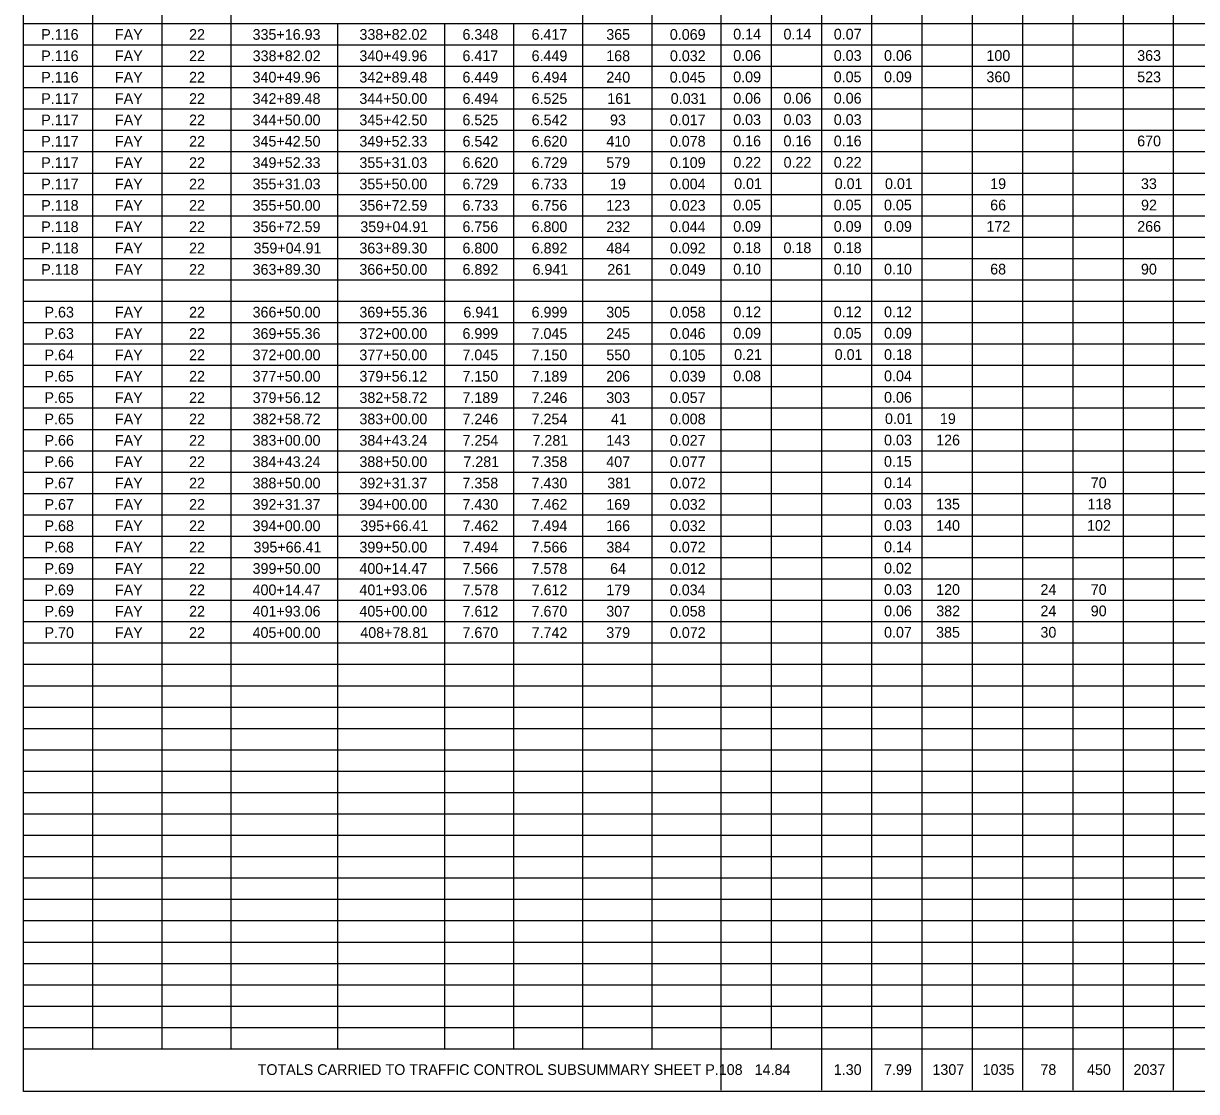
# Model space of a CAD drawing. Extents: x 12522 to 13018, y 1124 to 1902.
# Drawn here: x 12873.15 to 12888.52, y 1804.65 to 1818.65 of the extents above; entities that cross this region are included whole.
import ezdxf

# ---------------------------------------------------------------- set-up
doc = ezdxf.new("R2010")
doc.units = 0
for name, color, linetype in [('SC_Scratch1', 7, 'Continuous'), ('SH_Data', 7, 'Continuous'), ('SH_Text', 7, 'Continuous')]:
    doc.layers.add(name, color=color, linetype=linetype)

msp = doc.modelspace()

# ---------------------------------------------------------------- linework, layer by layer
at = {"layer": 'SC_Scratch1'}
msp.add_lwpolyline([(12873.148, 1825.65), (12903.648, 1825.65), (12903.648, 1804.65), (12873.148, 1804.65)], close=True, dxfattribs=at)
at = {"layer": 'SH_Data'}
for p, q in [((12882.289, 1825.65), (12882.289, 1804.667)), ((12875.865, 1825.09), (12875.865, 1805.21)), ((12880.477, 1825.09), (12880.477, 1805.21)), ((12881.383, 1825.09), (12881.383, 1805.21)), ((12883.607, 1825.09), (12883.607, 1804.667)), ((12884.265, 1825.09), (12884.265, 1804.667)), ((12884.924, 1825.09), (12884.924, 1804.667)), ((12885.583, 1825.09), (12885.583, 1804.667)), ((12886.242, 1825.09), (12886.242, 1804.667)), ((12886.901, 1825.09), (12886.901, 1804.667)), ((12887.56, 1825.09), (12887.56, 1804.667)), ((12888.218, 1825.09), (12888.218, 1804.667)), ((12882.948, 1822.85), (12882.948, 1805.21)), ((12874.054, 1821.73), (12874.054, 1805.21)), ((12874.96, 1821.73), (12874.96, 1805.21)), ((12873.148, 1818.65), (12903.668, 1818.65)), ((12877.265, 1818.65), (12877.265, 1805.21)), ((12878.665, 1818.65), (12878.665, 1805.21)), ((12879.571, 1818.65), (12879.571, 1805.21)), ((12873.148, 1818.37), (12903.668, 1818.37)), ((12873.148, 1818.09), (12903.668, 1818.09)), ((12873.148, 1817.81), (12903.668, 1817.81)), ((12873.148, 1817.53), (12903.668, 1817.53)), ((12873.148, 1817.25), (12903.668, 1817.25)), ((12873.148, 1816.97), (12903.668, 1816.97)), ((12873.148, 1816.69), (12903.668, 1816.69)), ((12873.148, 1816.41), (12903.668, 1816.41)), ((12873.148, 1816.13), (12903.668, 1816.13)), ((12873.148, 1815.85), (12903.668, 1815.85)), ((12873.148, 1815.57), (12903.668, 1815.57)), ((12873.148, 1815.29), (12903.668, 1815.29)), ((12873.148, 1815.01), (12903.668, 1815.01)), ((12873.148, 1814.73), (12903.668, 1814.73)), ((12873.148, 1814.45), (12903.668, 1814.45)), ((12873.148, 1814.17), (12903.668, 1814.17)), ((12873.148, 1813.89), (12903.668, 1813.89)), ((12873.148, 1813.61), (12903.668, 1813.61)), ((12873.148, 1813.33), (12903.668, 1813.33)), ((12873.148, 1813.05), (12903.668, 1813.05)), ((12873.148, 1812.77), (12903.668, 1812.77)), ((12873.148, 1812.49), (12903.668, 1812.49)), ((12873.148, 1812.21), (12903.668, 1812.21)), ((12873.148, 1811.93), (12903.668, 1811.93)), ((12873.148, 1811.65), (12903.668, 1811.65)), ((12873.148, 1811.37), (12903.668, 1811.37)), ((12873.148, 1811.09), (12903.668, 1811.09)), ((12873.148, 1810.81), (12903.668, 1810.81)), ((12873.148, 1810.53), (12903.668, 1810.53)), ((12873.148, 1810.25), (12903.668, 1810.25)), ((12873.148, 1809.97), (12903.668, 1809.97)), ((12873.148, 1809.69), (12903.668, 1809.69)), ((12873.148, 1809.41), (12903.668, 1809.41)), ((12873.148, 1809.13), (12903.668, 1809.13)), ((12873.148, 1808.85), (12903.668, 1808.85)), ((12873.148, 1808.57), (12903.668, 1808.57)), ((12873.148, 1808.29), (12903.668, 1808.29)), ((12873.148, 1808.01), (12903.668, 1808.01)), ((12873.148, 1807.73), (12903.668, 1807.73)), ((12873.148, 1807.45), (12903.668, 1807.45)), ((12873.148, 1807.17), (12903.668, 1807.17)), ((12873.148, 1806.89), (12903.668, 1806.89)), ((12873.148, 1806.61), (12903.668, 1806.61)), ((12873.148, 1806.33), (12903.668, 1806.33)), ((12873.148, 1806.05), (12903.668, 1806.05)), ((12873.148, 1805.77), (12903.668, 1805.77)), ((12873.148, 1805.49), (12903.668, 1805.49)), ((12873.148, 1805.21), (12903.668, 1805.21))]:
    msp.add_line(p, q, dxfattribs=at)

# ---------------------------------------------------------------- texts
at = {"layer": 'SH_Text'}
for s, p in [('P.116', (12873.381, 1818.436)), ('FAY', (12874.347, 1818.436)), ('22', (12875.319, 1818.436)), ('335+16.93', (12876.151, 1818.436)), ('338+82.02', (12877.552, 1818.436)), ('6.348', (12878.902, 1818.436)), ('6.417', (12879.808, 1818.436)), ('365', (12880.787, 1818.436)), ('0.069', (12881.62, 1818.436)), ('0.14', (12882.451, 1818.44)), ('0.14', (12883.11, 1818.44)), ('0.07', (12883.769, 1818.44)), ('P.116', (12873.381, 1818.156)), ('FAY', (12874.347, 1818.156)), ('22', (12875.319, 1818.156)), ('338+82.02', (12876.152, 1818.156)), ('340+49.96', (12877.551, 1818.156)), ('6.417', (12878.902, 1818.156)), ('6.449', (12879.808, 1818.156)), ('168', (12880.787, 1818.156)), ('0.032', (12881.621, 1818.156)), ('0.06', (12882.451, 1818.16)), ('0.03', (12883.769, 1818.16)), ('0.06', (12884.428, 1818.16)), ('100', (12885.77, 1818.16)), ('363', (12887.746, 1818.16)), ('P.116', (12873.381, 1817.876)), ('FAY', (12874.347, 1817.876)), ('22', (12875.319, 1817.876)), ('340+49.96', (12876.151, 1817.876)), ('342+89.48', (12877.551, 1817.876)), ('6.449', (12878.902, 1817.876)), ('6.494', (12879.808, 1817.876)), ('240', (12880.788, 1817.876)), ('0.045', (12881.619, 1817.876)), ('0.09', (12882.451, 1817.88)), ('0.05', (12883.768, 1817.88)), ('0.09', (12884.428, 1817.88)), ('360', (12885.77, 1817.88)), ('523', (12887.746, 1817.88)), ('P.117', (12873.381, 1817.596)), ('FAY', (12874.347, 1817.596)), ('22', (12875.319, 1817.596)), ('342+89.48', (12876.151, 1817.596)), ('344+50.00', (12877.551, 1817.596)), ('6.494', (12878.903, 1817.596)), ('6.525', (12879.808, 1817.596)), ('161', (12880.8, 1817.596)), ('0.031', (12881.632, 1817.596)), ('0.06', (12882.451, 1817.6)), ('0.06', (12883.11, 1817.6)), ('0.06', (12883.769, 1817.6)), ('P.117', (12873.381, 1817.316)), ('FAY', (12874.347, 1817.316)), ('22', (12875.319, 1817.316)), ('344+50.00', (12876.151, 1817.316)), ('345+42.50', (12877.551, 1817.316)), ('6.525', (12878.902, 1817.316)), ('6.542', (12879.809, 1817.316)), ('93', (12880.836, 1817.316)), ('0.017', (12881.62, 1817.316)), ('0.03', (12882.451, 1817.32)), ('0.03', (12883.11, 1817.32)), ('0.03', (12883.769, 1817.32)), ('P.117', (12873.381, 1817.036)), ('FAY', (12874.347, 1817.036)), ('22', (12875.319, 1817.036)), ('345+42.50', (12876.151, 1817.036)), ('349+52.33', (12877.551, 1817.036)), ('6.542', (12878.903, 1817.036)), ('6.620', (12879.808, 1817.036)), ('410', (12880.788, 1817.036)), ('0.078', (12881.62, 1817.036)), ('0.16', (12882.451, 1817.04)), ('0.16', (12883.11, 1817.04)), ('0.16', (12883.769, 1817.04)), ('670', (12887.746, 1817.04)), ('P.117', (12873.381, 1816.756)), ('FAY', (12874.347, 1816.756)), ('22', (12875.319, 1816.756)), ('349+52.33', (12876.151, 1816.756)), ('355+31.03', (12877.551, 1816.756)), ('6.620', (12878.902, 1816.756)), ('6.729', (12879.808, 1816.756)), ('579', (12880.787, 1816.756)), ('0.109', (12881.62, 1816.756)), ('0.22', (12882.452, 1816.76)), ('0.22', (12883.111, 1816.76)), ('0.22', (12883.769, 1816.76)), ('P.117', (12873.381, 1816.476)), ('FAY', (12874.347, 1816.476)), ('22', (12875.319, 1816.476)), ('355+31.03', (12876.151, 1816.476)), ('355+50.00', (12877.551, 1816.476)), ('6.729', (12878.902, 1816.476)), ('6.733', (12879.808, 1816.476)), ('19', (12880.836, 1816.476)), ('0.004', (12881.62, 1816.476)), ('0.01', (12882.463, 1816.48)), ('0.01', (12883.781, 1816.48)), ('0.01', (12884.44, 1816.48)), ('19', (12885.819, 1816.48)), ('33', (12887.795, 1816.48)), ('P.118', (12873.381, 1816.196)), ('FAY', (12874.347, 1816.196)), ('22', (12875.319, 1816.196)), ('355+50.00', (12876.151, 1816.196)), ('356+72.59', (12877.551, 1816.196)), ('6.733', (12878.902, 1816.196)), ('6.756', (12879.808, 1816.196)), ('123', (12880.787, 1816.196)), ('0.023', (12881.62, 1816.196)), ('0.05', (12882.451, 1816.2)), ('0.05', (12883.768, 1816.2)), ('0.05', (12884.427, 1816.2)), ('66', (12885.819, 1816.2)), ('92', (12887.796, 1816.2)), ('P.118', (12873.381, 1815.916)), ('FAY', (12874.347, 1815.916)), ('22', (12875.319, 1815.916)), ('356+72.59', (12876.151, 1815.916)), ('359+04.91', (12877.563, 1815.916)), ('6.756', (12878.902, 1815.916)), ('6.800', (12879.808, 1815.916)), ('232', (12880.788, 1815.916)), ('0.044', (12881.62, 1815.916)), ('0.09', (12882.451, 1815.92)), ('0.09', (12883.769, 1815.92)), ('0.09', (12884.428, 1815.92)), ('172', (12885.77, 1815.92)), ('266', (12887.746, 1815.92)), ('P.118', (12873.381, 1815.636)), ('FAY', (12874.347, 1815.636)), ('22', (12875.319, 1815.636)), ('359+04.91', (12876.163, 1815.636)), ('363+89.30', (12877.551, 1815.636)), ('6.800', (12878.902, 1815.636)), ('6.892', (12879.809, 1815.636)), ('484', (12880.788, 1815.636)), ('0.092', (12881.621, 1815.636)), ('0.18', (12882.451, 1815.64)), ('0.18', (12883.11, 1815.64)), ('0.18', (12883.769, 1815.64)), ('P.118', (12873.381, 1815.356)), ('FAY', (12874.347, 1815.356)), ('22', (12875.319, 1815.356)), ('363+89.30', (12876.151, 1815.356)), ('366+50.00', (12877.551, 1815.356)), ('6.892', (12878.903, 1815.356)), ('6.941', (12879.82, 1815.356)), ('261', (12880.8, 1815.356)), ('0.049', (12881.62, 1815.356)), ('0.10', (12882.451, 1815.36)), ('0.10', (12883.769, 1815.36)), ('0.10', (12884.428, 1815.36)), ('68', (12885.819, 1815.36)), ('90', (12887.795, 1815.36)), ('P.63', (12873.424, 1814.796)), ('FAY', (12874.347, 1814.796)), ('22', (12875.319, 1814.796)), ('366+50.00', (12876.151, 1814.796)), ('369+55.36', (12877.551, 1814.796)), ('6.941', (12878.914, 1814.796)), ('6.999', (12879.808, 1814.796)), ('305', (12880.787, 1814.796)), ('0.058', (12881.62, 1814.796)), ('0.12', (12882.452, 1814.8)), ('0.12', (12883.769, 1814.8)), ('0.12', (12884.428, 1814.8)), ('P.63', (12873.424, 1814.516)), ('FAY', (12874.347, 1814.516)), ('22', (12875.319, 1814.516)), ('369+55.36', (12876.151, 1814.516)), ('372+00.00', (12877.551, 1814.516)), ('6.999', (12878.902, 1814.516)), ('7.045', (12879.808, 1814.516)), ('245', (12880.787, 1814.516)), ('0.046', (12881.62, 1814.516)), ('0.09', (12882.451, 1814.52)), ('0.05', (12883.768, 1814.52)), ('0.09', (12884.428, 1814.52)), ('P.64', (12873.424, 1814.236)), ('FAY', (12874.347, 1814.236)), ('22', (12875.319, 1814.236)), ('372+00.00', (12876.151, 1814.236)), ('377+50.00', (12877.551, 1814.236)), ('7.045', (12878.902, 1814.236)), ('7.150', (12879.808, 1814.236)), ('550', (12880.788, 1814.236)), ('0.105', (12881.619, 1814.236)), ('0.21', (12882.463, 1814.24)), ('0.01', (12883.781, 1814.24)), ('0.18', (12884.428, 1814.24)), ('P.65', (12873.423, 1813.956)), ('FAY', (12874.347, 1813.956)), ('22', (12875.319, 1813.956)), ('377+50.00', (12876.151, 1813.956)), ('379+56.12', (12877.552, 1813.956)), ('7.150', (12878.902, 1813.956)), ('7.189', (12879.808, 1813.956)), ('206', (12880.787, 1813.956)), ('0.039', (12881.62, 1813.956)), ('0.08', (12882.451, 1813.96)), ('0.04', (12884.428, 1813.96)), ('P.65', (12873.423, 1813.676)), ('FAY', (12874.347, 1813.676)), ('22', (12875.319, 1813.676)), ('379+56.12', (12876.152, 1813.676)), ('382+58.72', (12877.552, 1813.676)), ('7.189', (12878.902, 1813.676)), ('7.246', (12879.808, 1813.676)), ('303', (12880.787, 1813.676)), ('0.057', (12881.62, 1813.676)), ('0.06', (12884.428, 1813.68)), ('P.65', (12873.423, 1813.396)), ('FAY', (12874.347, 1813.396)), ('22', (12875.319, 1813.396)), ('382+58.72', (12876.152, 1813.396)), ('383+00.00', (12877.551, 1813.396)), ('7.246', (12878.902, 1813.396)), ('7.254', (12879.808, 1813.396)), ('41', (12880.848, 1813.396)), ('0.008', (12881.62, 1813.396)), ('0.01', (12884.44, 1813.4)), ('19', (12885.16, 1813.4)), ('P.66', (12873.424, 1813.116)), ('FAY', (12874.347, 1813.116)), ('22', (12875.319, 1813.116)), ('383+00.00', (12876.151, 1813.116)), ('384+43.24', (12877.551, 1813.116)), ('7.254', (12878.903, 1813.116)), ('7.281', (12879.82, 1813.116)), ('143', (12880.787, 1813.116)), ('0.027', (12881.62, 1813.116)), ('0.03', (12884.428, 1813.12)), ('126', (12885.111, 1813.12)), ('P.66', (12873.424, 1812.836)), ('FAY', (12874.347, 1812.836)), ('22', (12875.319, 1812.836)), ('384+43.24', (12876.151, 1812.836)), ('388+50.00', (12877.551, 1812.836)), ('7.281', (12878.914, 1812.836)), ('7.358', (12879.808, 1812.836)), ('407', (12880.787, 1812.836)), ('0.077', (12881.62, 1812.836)), ('0.15', (12884.427, 1812.84)), ('P.67', (12873.424, 1812.556)), ('FAY', (12874.347, 1812.556)), ('22', (12875.319, 1812.556)), ('388+50.00', (12876.151, 1812.556)), ('392+31.37', (12877.551, 1812.556)), ('7.358', (12878.902, 1812.556)), ('7.430', (12879.808, 1812.556)), ('381', (12880.8, 1812.556)), ('0.072', (12881.621, 1812.556)), ('0.14', (12884.428, 1812.56)), ('70', (12887.137, 1812.56)), ('P.67', (12873.424, 1812.276)), ('FAY', (12874.347, 1812.276)), ('22', (12875.319, 1812.276)), ('392+31.37', (12876.151, 1812.276)), ('394+00.00', (12877.551, 1812.276)), ('7.430', (12878.902, 1812.276)), ('7.462', (12879.809, 1812.276)), ('169', (12880.787, 1812.276)), ('0.032', (12881.621, 1812.276)), ('0.03', (12884.428, 1812.28)), ('135', (12885.11, 1812.28)), ('118', (12887.094, 1812.28)), ('P.68', (12873.424, 1811.996)), ('FAY', (12874.347, 1811.996)), ('22', (12875.319, 1811.996)), ('394+00.00', (12876.151, 1811.996)), ('395+66.41', (12877.563, 1811.996)), ('7.462', (12878.903, 1811.996)), ('7.494', (12879.808, 1811.996)), ('166', (12880.787, 1811.996)), ('0.032', (12881.621, 1811.996)), ('0.03', (12884.428, 1812)), ('140', (12885.111, 1812)), ('102', (12887.088, 1812)), ('P.68', (12873.424, 1811.716)), ('FAY', (12874.347, 1811.716)), ('22', (12875.319, 1811.716)), ('395+66.41', (12876.163, 1811.716)), ('399+50.00', (12877.551, 1811.716)), ('7.494', (12878.903, 1811.716)), ('7.566', (12879.808, 1811.716)), ('384', (12880.788, 1811.716)), ('0.072', (12881.621, 1811.716)), ('0.14', (12884.428, 1811.72)), ('P.69', (12873.424, 1811.436)), ('22', (12875.319, 1811.436)), ('399+50.00', (12876.151, 1811.436)), ('400+14.47', (12877.551, 1811.436)), ('7.566', (12878.902, 1811.436)), ('7.578', (12879.808, 1811.436)), ('64', (12880.837, 1811.436)), ('0.012', (12881.621, 1811.436)), ('0.02', (12884.428, 1811.44)), ('FAY', (12874.347, 1811.436)), ('P.69', (12873.424, 1811.156)), ('FAY', (12874.347, 1811.156)), ('22', (12875.319, 1811.156)), ('400+14.47', (12876.151, 1811.156)), ('401+93.06', (12877.551, 1811.156)), ('7.578', (12878.902, 1811.156)), ('7.612', (12879.809, 1811.156)), ('179', (12880.787, 1811.156)), ('0.034', (12881.62, 1811.156)), ('0.03', (12884.428, 1811.16)), ('120', (12885.111, 1811.16)), ('24', (12886.478, 1811.16)), ('70', (12887.137, 1811.16)), ('P.69', (12873.424, 1810.876)), ('FAY', (12874.347, 1810.876)), ('22', (12875.319, 1810.876)), ('401+93.06', (12876.151, 1810.876)), ('405+00.00', (12877.551, 1810.876)), ('7.612', (12878.903, 1810.876)), ('7.670', (12879.808, 1810.876)), ('307', (12880.787, 1810.876)), ('0.058', (12881.62, 1810.876)), ('0.06', (12884.428, 1810.88)), ('382', (12885.112, 1810.88)), ('24', (12886.478, 1810.88)), ('90', (12887.137, 1810.88)), ('P.70', (12873.424, 1810.596)), ('FAY', (12874.347, 1810.596)), ('22', (12875.319, 1810.596)), ('405+00.00', (12876.151, 1810.596)), ('408+78.81', (12877.563, 1810.596)), ('7.670', (12878.902, 1810.596)), ('7.742', (12879.809, 1810.596)), ('379', (12880.787, 1810.596)), ('0.072', (12881.621, 1810.596)), ('0.07', (12884.428, 1810.6)), ('385', (12885.11, 1810.6)), ('30', (12886.478, 1810.6)), ('TOTALS CARRIED TO TRAFFIC CONTROL SUBSUMMARY SHEET P.108', (12876.218, 1804.868)), ('14.84', (12882.732, 1804.868)), ('1.30', (12883.769, 1804.868)), ('7.99', (12884.428, 1804.868)), ('1307', (12885.062, 1804.868)), ('1035', (12885.72, 1804.868)), ('78', (12886.477, 1804.868)), ('450', (12887.088, 1804.868)), ('2037', (12887.697, 1804.868))]:
    msp.add_text(s, height=0.14, dxfattribs=at).set_placement(p)

doc.saveas('drawing.dxf')
